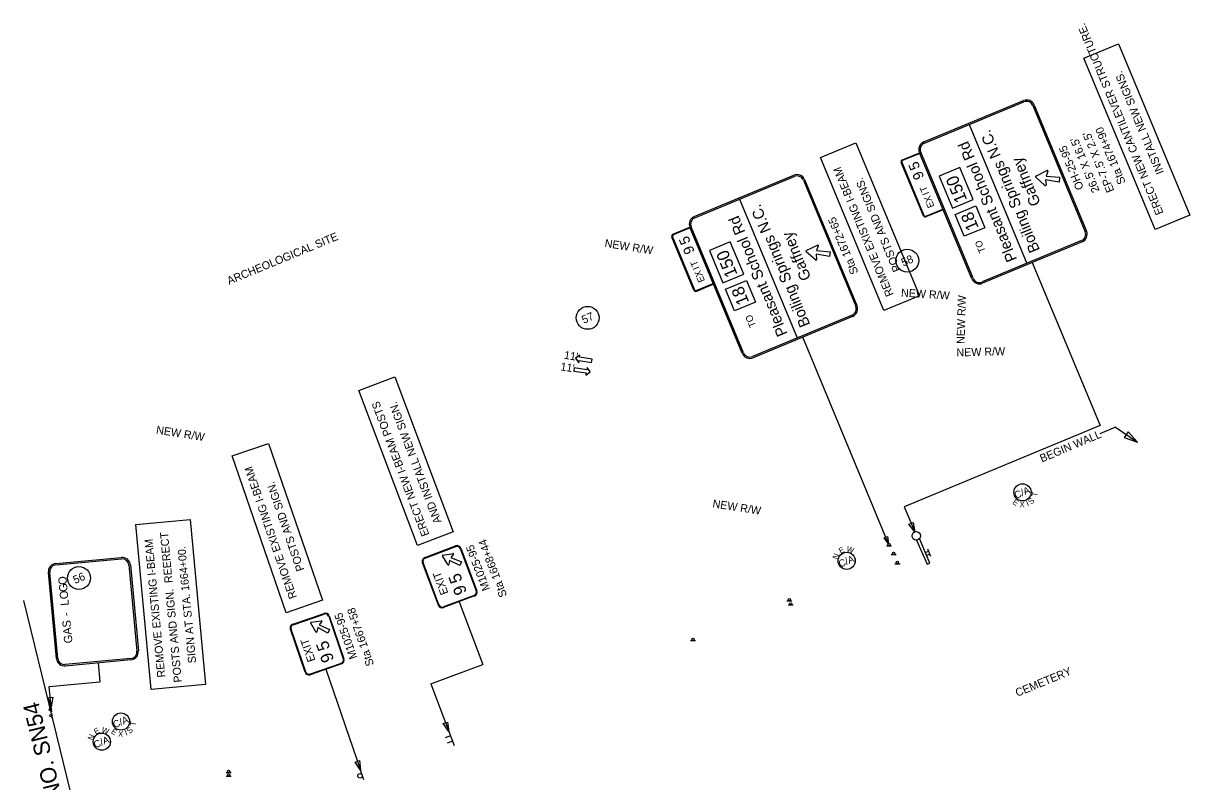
# Model space of a CAD drawing. Extents: x 1813391 to 1815007, y 1189909 to 1191222.
# Drawn here: x 1813391 to 1814411, y 1190407 to 1191071 of the extents above; entities that cross this region are included whole.
import ezdxf

# ---------------------------------------------------------------- set-up
doc = ezdxf.new("R2010")
doc.units = 0
for name, color, linetype in [('RD_EX_DV_Prop_txCode', 7, 'Continuous'), ('RD_EX_DV_TX_Prop', 7, 'Continuous'), ('RD_PD_Final_LnLine', 7, 'Continuous'), ('RD_PD_Final_TX', 7, 'Continuous'), ('RD_PD_RW_TX', 7, 'Continuous'), ('RD_SHT_MatchLine', 7, 'Continuous'), ('RD_SHT_TX', 7, 'Continuous'), ('RD_Sketch10', 7, 'Continuous'), ('RD_Sketch8', 7, 'Continuous'), ('SN_P_Signs', 7, 'Continuous'), ('TERMINATOR', 7, 'Continuous')]:
    doc.layers.add(name, color=color, linetype=linetype)

# ---------------------------------------------------------------- blocks, each defined once
blk = doc.blocks.new('SARRW2')
at = {"layer": 'RD_PD_Final_LnLine'}
blk.add_lwpolyline([(-12, 1.2), (-12, -1.2), (-2.83, -1.2), (-2.83, -2.83), (0, 0), (-2.83, 2.83), (-2.83, 1.2)], close=True, dxfattribs=at)

msp = doc.modelspace()

# ---------------------------------------------------------------- linework, layer by layer
at = {"layer": 'RD_EX_DV_TX_Prop'}
for centre in [(1814164.1, 1190863), (1813884.5, 1190812.9), (1813439.4, 1190585.3)]:
    msp.add_circle(centre, 10, dxfattribs=at)
at = {"layer": 'RD_PD_Final_TX'}
for q in [(1814332.5, 1190711.4), (1814365.5, 1190704)]:
    msp.add_line((1814346.2, 1190717.2), q, dxfattribs=at)
at = {"layer": 'RD_SHT_MatchLine'}
msp.add_line((1813390.8, 1190565.5), (1813552.1, 1189908.7), dxfattribs=at)
at = {"layer": 'RD_Sketch10'}
for centre in [(1814111.1, 1190600.3), (1813459.4, 1190442.1)]:
    msp.add_circle(centre, 7.5, dxfattribs=at)
at = {"layer": 'RD_Sketch8'}
for centre in [(1814264.9, 1190660.3), (1813476.2, 1190459.7)]:
    msp.add_circle(centre, 7.5, dxfattribs=at)
at = {"layer": 'SN_P_Signs'}
for p, q in [((1814218.3, 1190982), (1814268.7, 1190860.6)), ((1814088.1, 1190953.1), (1814119.1, 1190966)), ((1814119.1, 1190966), (1814174.8, 1190832.1)), ((1814143.7, 1190819.2), (1814088.1, 1190953.1)), ((1814210.2, 1190944.5), (1814192, 1190936.9)), ((1814221.9, 1190916.4), (1814210.2, 1190944.5)), ((1814192, 1190936.9), (1814203.7, 1190908.8)), ((1814017.4, 1190916.7), (1814067.9, 1190795.4)), ((1814203.7, 1190908.8), (1814221.9, 1190916.4)), ((1814206, 1190903.2), (1814224.2, 1190910.8)), ((1814224.2, 1190910.8), (1814232.1, 1190891.8)), ((1814213.9, 1190884.3), (1814206, 1190903.2)), ((1814232.1, 1190891.8), (1814213.9, 1190884.3)), ((1814009.3, 1190879.3), (1813991.2, 1190871.7)), ((1814021, 1190851.1), (1814009.3, 1190879.3)), ((1813991.2, 1190871.7), (1814002.9, 1190843.6)), ((1814273.5, 1190861.3), (1814332.8, 1190718.7)), ((1814002.9, 1190843.6), (1814021, 1190851.1)), ((1814005.2, 1190838), (1814023.4, 1190845.5)), ((1814013, 1190819.1), (1814005.2, 1190838)), ((1814023.4, 1190845.5), (1814031.2, 1190826.6)), ((1814174.8, 1190832.1), (1814143.7, 1190819.2)), ((1814031.2, 1190826.6), (1814013, 1190819.1)), ((1814147.8, 1190615.3), (1814072.7, 1190796.1)), ((1813684.3, 1190749.4), (1813715.7, 1190761.3)), ((1813715.7, 1190761.3), (1813766.9, 1190625.6)), ((1813735.5, 1190613.7), (1813684.3, 1190749.4)), ((1814332.8, 1190718.7), (1814161.5, 1190647.5)), ((1813573.6, 1190692.1), (1813605.4, 1190703)), ((1813605.4, 1190703), (1813652.5, 1190565.8)), ((1813620.7, 1190554.9), (1813573.6, 1190692.1)), ((1814161.5, 1190647.5), (1814170.6, 1190625.6)), ((1813489.2, 1190632.1), (1813536.6, 1190636.5)), ((1813536.6, 1190636.5), (1813550, 1190492.1)), ((1813502.6, 1190487.7), (1813489.2, 1190632.1)), ((1813766.9, 1190625.6), (1813735.5, 1190613.7)), ((1813742, 1190603.2), (1813768.9, 1190613.4)), ((1814145.9, 1190613.4), (1814150.4, 1190613.4)), ((1813742.2, 1190602.6), (1813769.2, 1190612.8)), ((1813773, 1190611.1), (1813787, 1190574)), ((1813773.6, 1190611.3), (1813787.6, 1190574.2)), ((1814149.9, 1190605.8), (1814154.4, 1190605.8)), ((1814180, 1190607.7), (1814182.6, 1190608.8)), ((1814181.1, 1190605.2), (1814183.6, 1190606.3)), ((1814181.7, 1190610.7), (1814184.5, 1190604.3)), ((1813753.9, 1190561.5), (1813739.9, 1190598.6)), ((1813754.4, 1190561.7), (1813740.5, 1190598.8)), ((1814153.3, 1190597.8), (1814157.8, 1190597.8)), ((1813652.5, 1190565.8), (1813620.7, 1190554.9)), ((1813785.2, 1190570.1), (1813758.3, 1190560)), ((1813785.5, 1190569.6), (1813758.5, 1190559.4)), ((1813772, 1190564.5), (1813792.7, 1190509.7)), ((1814058.7, 1190565.3), (1814063.2, 1190565.3)), ((1813626.6, 1190545), (1813653.9, 1190554.3)), ((1813626.8, 1190544.4), (1813654.1, 1190553.8)), ((1813657.9, 1190551.9), (1813670.7, 1190514.5)), ((1813658.4, 1190552.1), (1813671.3, 1190514.6)), ((1814059.8, 1190561.7), (1814064.3, 1190561.7)), ((1813637.2, 1190503), (1813624.4, 1190540.4)), ((1813637.8, 1190503.2), (1813625, 1190540.6)), ((1813974.4, 1190530.6), (1813978.9, 1190530.6)), ((1813456.2, 1190511), (1813457.7, 1190494.5)), ((1813668.9, 1190510.6), (1813641.6, 1190501.3)), ((1813669.1, 1190510.1), (1813641.8, 1190500.7)), ((1813655.4, 1190505.4), (1813685.7, 1190417.1)), ((1813747.3, 1190492.6), (1813792.7, 1190509.7)), ((1813413.5, 1190490.3), (1813457.7, 1190494.5)), ((1813550, 1190492.1), (1813502.6, 1190487.7)), ((1813747.3, 1190492.6), (1813763, 1190450.9)), ((1813415.2, 1190472.6), (1813413.5, 1190490.3)), ((1813415.6, 1190468.1), (1813415.2, 1190472.6)), ((1813416.1, 1190462.6), (1813415.7, 1190467.1)), ((1813763, 1190450.9), (1813767.6, 1190438.7)), ((1813764.4, 1190447.3), (1813759.7, 1190445.5)), ((1813766.1, 1190442.6), (1813761.5, 1190440.8)), ((1813568.1, 1190415.1), (1813572.6, 1190415.1)), ((1813568.1, 1190412), (1813572.6, 1190412)), ((1813688.7, 1190408.6), (1813685.7, 1190417.1))]:
    msp.add_line(p, q, dxfattribs=at)
for points in [[(1814380.9, 1190890.1), (1814318.6, 1191040.1), (1814348.9, 1191052.7), (1814411.2, 1190902.7)], [(1814169.2, 1190634), (1814170.6, 1190625.6), (1814165.4, 1190632.3)], [(1814146.9, 1190621.6), (1814147.8, 1190615.3), (1814144, 1190620.4)], [(1813416.5, 1190480.9), (1813415.2, 1190472.6), (1813412.4, 1190480.5)], [(1813762, 1190459.3), (1813763, 1190450.9), (1813758.2, 1190457.9)], [(1813685, 1190425.6), (1813685.7, 1190417.1), (1813681.1, 1190424.2)]]:
    msp.add_lwpolyline(points, close=True, dxfattribs=at)
for points in [[(1814178.7, 1190966.8), (1814265.7, 1191003)], [(1814179.1, 1190965.7), (1814266.2, 1191001.9)], [(1814274, 1190998.6), (1814319.8, 1190888.3)], [(1814275.1, 1190999.1), (1814321, 1190888.8)], [(1814159.8, 1190951.2), (1814174.8, 1190957.4), (1814175, 1190956.8)], [(1814175, 1190956.8), (1814160, 1190950.6)], [(1814220.6, 1190847.1), (1814174.8, 1190957.4)], [(1814221.7, 1190847.5), (1814175.9, 1190957.9)], [(1814178.2, 1190902.3), (1814158.8, 1190948.8)], [(1814159.4, 1190949.1), (1814178.7, 1190902.5)], [(1814276.6, 1190937), (1814286.3, 1190941.8)], [(1814287.2, 1190941.1), (1814285.6, 1190936.9)], [(1813977.8, 1190901.6), (1814064.9, 1190937.8)], [(1813978.3, 1190900.5), (1814065.3, 1190936.7)], [(1814073.2, 1190933.4), (1814119, 1190823.1)], [(1814074.3, 1190933.9), (1814120.1, 1190823.6)], [(1814284.6, 1190928.8), (1814276.5, 1190936)], [(1814297.4, 1190935.9), (1814296.9, 1190931.7), (1814285.2, 1190933.7)], [(1814285.2, 1190933.7), (1814285.6, 1190929.3)], [(1814285.6, 1190936.9), (1814297.4, 1190935.9)], [(1814180.3, 1190901.9), (1814195.3, 1190908.1), (1814195.5, 1190907.5), (1814180.5, 1190901.3)], [(1813959, 1190886), (1813973.9, 1190892.2), (1813974.2, 1190891.6)], [(1813974.2, 1190891.6), (1813959.2, 1190885.4)], [(1814019.8, 1190781.9), (1813973.9, 1190892.2)], [(1814020.9, 1190782.3), (1813975, 1190892.6)], [(1813977.3, 1190837.1), (1813958, 1190883.6)], [(1813958.6, 1190883.8), (1813977.9, 1190837.3)], [(1814316.6, 1190880.5), (1814229.6, 1190844.3)], [(1814317.1, 1190879.4), (1814230, 1190843.2)], [(1814083.8, 1190863.6), (1814075.7, 1190870.8)], [(1814075.8, 1190871.8), (1814085.5, 1190876.6)], [(1814096.6, 1190870.7), (1814096, 1190866.5), (1814084.3, 1190868.5)], [(1814084.3, 1190868.5), (1814084.8, 1190864.1)], [(1814086.3, 1190875.9), (1814084.7, 1190871.7)], [(1814084.7, 1190871.7), (1814096.6, 1190870.7)], [(1813979.5, 1190836.7), (1813994.4, 1190842.9), (1813994.7, 1190842.3), (1813979.7, 1190836.1)], [(1814115.8, 1190815.3), (1814028.7, 1190779.1)], [(1814116.2, 1190814.2), (1814029.2, 1190778)], [(1814172.3, 1190618.5), (1814181.5, 1190597.3), (1814184, 1190598.4), (1814174.8, 1190619.8)], [(1813419.2, 1190597.9), (1813476.5, 1190603.3)], [(1813762.2, 1190597), (1813757.5, 1190604.6)], [(1813757.8, 1190605.3), (1813766.7, 1190606.8)], [(1813767.1, 1190606.1), (1813764.8, 1190603.2)], [(1813764.8, 1190603.2), (1813774.2, 1190599.5)], [(1813419.3, 1190596.7), (1813476.6, 1190602.1)], [(1813483.2, 1190596.7), (1813490.2, 1190521.4)], [(1813484.4, 1190596.8), (1813491.4, 1190521.5)], [(1813763.7, 1190600.7), (1813763.1, 1190597.1)], [(1813774.2, 1190599.5), (1813772.7, 1190596.2), (1813763.7, 1190600.7)], [(1813419.7, 1190514.8), (1813412.7, 1190590.1)], [(1813420.9, 1190514.9), (1813413.9, 1190590.2)], [(1813646.7, 1190538.1), (1813642.2, 1190545.9)], [(1813642.5, 1190546.6), (1813651.4, 1190547.8)], [(1813648.3, 1190541.9), (1813647.5, 1190538.3)], [(1813658.7, 1190540.3), (1813657.1, 1190537), (1813648.3, 1190541.9)], [(1813651.8, 1190547.1), (1813649.5, 1190544.3)], [(1813649.5, 1190544.3), (1813658.7, 1190540.3)], [(1813484.8, 1190514.9), (1813427.4, 1190509.5)], [(1813484.9, 1190513.7), (1813427.5, 1190508.3)]]:
    msp.add_lwpolyline(points, dxfattribs=at)
for centre, radius in [((1814172, 1190622.2), 3.71), ((1814148.2, 1190614.4), 1), ((1814152.1, 1190606.8), 1), ((1814155.5, 1190598.9), 1), ((1814061, 1190566.3), 1), ((1814062, 1190562.7), 1), ((1813976.7, 1190531.6), 1), ((1813414.4, 1190470.2), 1), ((1813414.9, 1190464.8), 1), ((1813570.3, 1190416.1), 1), ((1813570.4, 1190413), 1), ((1813685.3, 1190412.2), 2)]:
    msp.add_circle(centre, radius, dxfattribs=at)
for centre, radius, start, end in [((1814268.5, 1190996.3), 7.2, 22.5666, 112.5666), ((1814268.5, 1190996.3), 6, 22.5666, 112.5666), ((1814181.4, 1190960.2), 7.2, 112.5666, 202.5666), ((1814181.4, 1190960.2), 6, 112.5666, 202.5666), ((1814160.5, 1190949.5), 1.8, 112.5666, 202.5666), ((1814160.5, 1190949.5), 1.2, 112.5666, 202.5666), ((1814286.6, 1190941.3), 0.6, 339.1205, 116.586), ((1814067.6, 1190931.1), 7.2, 22.5666, 112.5666), ((1814067.6, 1190931.1), 6, 22.5666, 112.5666), ((1814276.9, 1190936.4), 0.6, 116.586, 228.5473), ((1814285, 1190929.2), 0.6, 228.5473, 6.0127), ((1813980.6, 1190894.9), 7.2, 112.5666, 202.5666), ((1813980.6, 1190894.9), 6, 112.5666, 202.5666), ((1814179.8, 1190903), 1.8, 202.5666, 292.5666), ((1814179.8, 1190903), 1.2, 202.5666, 292.5666), ((1814314.3, 1190886), 7.2, 292.5666, 22.5666), ((1813959.7, 1190884.3), 1.8, 112.5666, 202.5666), ((1813959.7, 1190884.3), 1.2, 112.5666, 202.5666), ((1814314.3, 1190886), 6, 292.5666, 22.5666), ((1814076.1, 1190871.2), 0.6, 116.586, 228.5473), ((1814085.8, 1190876.1), 0.6, 339.1205, 116.586), ((1814084.2, 1190864), 0.6, 228.5473, 6.0127), ((1814227.3, 1190849.8), 7.2, 202.5666, 292.5666), ((1814227.3, 1190849.8), 6, 202.5666, 292.5666), ((1813979, 1190837.8), 1.8, 202.5666, 292.5666), ((1813979, 1190837.8), 1.2, 202.5666, 292.5666), ((1814113.5, 1190820.8), 6, 292.5666, 22.5666), ((1814113.5, 1190820.8), 7.2, 292.5666, 22.5666), ((1814026.4, 1190784.6), 7.2, 202.5666, 292.5666), ((1814026.4, 1190784.6), 6, 202.5666, 292.5666), ((1813770.2, 1190610), 3.6, 20.6671, 110.6671), ((1813770.2, 1190610), 3, 20.6671, 110.6671), ((1813477.2, 1190596.1), 7.2, 5.3197, 95.3197), ((1813743.3, 1190599.8), 3.6, 110.6671, 200.6671), ((1813757.9, 1190604.9), 0.45, 99.4892, 211.845), ((1813766.8, 1190606.3), 0.45, 321.705, 99.4892), ((1813419.8, 1190590.8), 7.2, 95.3197, 185.3197), ((1813419.8, 1190590.8), 6, 95.3197, 185.3197), ((1813477.2, 1190596.1), 6, 5.3197, 95.3197), ((1813743.3, 1190599.8), 3, 110.6671, 200.6671), ((1813762.6, 1190597.2), 0.45, 211.845, 349.6292), ((1813784.2, 1190572.9), 3, 290.6671, 20.6671), ((1813784.2, 1190572.9), 3.6, 290.6671, 20.6671), ((1813655, 1190550.9), 3.6, 18.9395, 108.9395), ((1813655, 1190550.9), 3, 18.9395, 108.9395), ((1813757.2, 1190562.8), 3.6, 200.6671, 290.6671), ((1813757.2, 1190562.8), 3, 200.6671, 290.6671), ((1813627.8, 1190541.6), 3.6, 108.9395, 198.9395), ((1813627.8, 1190541.6), 3, 108.9395, 198.9395), ((1813642.5, 1190546.2), 0.45, 97.7616, 210.1174), ((1813651.5, 1190547.4), 0.45, 319.9774, 97.7616), ((1813647.1, 1190538.4), 0.45, 210.1174, 347.9016), ((1813484.2, 1190520.8), 6, 275.3197, 5.3197), ((1813484.2, 1190520.8), 7.2, 275.3197, 5.3197), ((1813426.9, 1190515.5), 7.2, 185.3197, 275.3197), ((1813426.9, 1190515.5), 6, 185.3197, 275.3197), ((1813667.9, 1190513.5), 3, 288.9395, 18.9395), ((1813667.9, 1190513.5), 3.6, 288.9395, 18.9395), ((1813640.7, 1190504.1), 3.6, 198.9395, 288.9395), ((1813640.7, 1190504.1), 3, 198.9395, 288.9395)]:
    msp.add_arc(centre, radius, start, end, dxfattribs=at)
at = {"layer": 'TERMINATOR'}
msp.add_lwpolyline([(1814353.9, 1190708.3), (1814365.5, 1190704), (1814357.3, 1190713.2)], close=True, dxfattribs=at)

# ---------------------------------------------------------------- block references
at = {"layer": 'RD_PD_Final_LnLine'}
for p, xscale, yscale, rotation in [((1813873.9, 1190777.5), 1.2000000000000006, 1.2000000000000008, 171.59372332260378), ((1813886.8, 1190765.6), 1.2000000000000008, 1.200000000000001, -8.40627667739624)]:
    msp.add_blockref('SARRW2', p, dxfattribs=dict(at, xscale=xscale, yscale=yscale, rotation=rotation))

# ---------------------------------------------------------------- texts
at = {"layer": 'RD_EX_DV_Prop_txCode'}
for s, p in [('58', (1814160.7, 1190857.7)), ('57', (1813881.1, 1190807.6)), ('56', (1813436.1, 1190580))]:
    msp.add_text(s, height=7, rotation=23.7538, dxfattribs=at).set_placement(p)
at = {"layer": 'RD_PD_Final_TX'}
for s, rotation, p in [('ARCHEOLOGICAL SITE', 22.4268, (1813570.7, 1190841.8)), ("11'", 350.8557, (1813863.4, 1190777.2)), ("11'", 350.8557, (1813860.3, 1190767.1)), ('BEGIN WALL', 22.8166, (1814281.9, 1190686.3)), ('CEMETERY', 22.4268, (1814260.4, 1190481.3))]:
    msp.add_text(s, height=7, rotation=rotation, dxfattribs=at).set_placement(p)
at = {"layer": 'RD_PD_RW_TX'}
for rotation, p in [(351.0437, (1813899, 1190875)), (356.3248, (1814158.5, 1190831.6)), (88.2894, (1814214.2, 1190790)), (1.5746, (1814207.2, 1190779.1)), (351.0437, (1813506.6, 1190711.7)), (351.0437, (1813993.4, 1190647.2))]:
    msp.add_text('NEW R/W', height=7, rotation=rotation, dxfattribs=at).set_placement(p)
at = {"layer": 'RD_SHT_TX'}
msp.add_text('MATCHLINE STA. 1665+00 SEE SHEET NO. SN54', height=14.173, rotation=103.9067, dxfattribs=at).set_placement((1813509.6, 1190050.9))
at = {"layer": 'RD_Sketch10'}
for s, height, rotation, p in [('W', 5, 341.8692, (1814110.5, 1190608.6)), ('N', 5, 67.4364, (1814103, 1190601.1)), ('E', 5, 26.8996, (1814105.8, 1190606.4)), ('C/A', 6.25, 22.5666, (1814105.5, 1190594.4)), ('E', 5, 26.8996, (1813454.1, 1190448.2)), ('W', 5, 341.8692, (1813458.8, 1190450.4)), ('N', 5, 67.4364, (1813451.4, 1190442.9)), ('C/A', 6.25, 22.5666, (1813453.8, 1190436.2))]:
    msp.add_text(s, height=height, rotation=rotation, dxfattribs=at).set_placement(p)
at = {"layer": 'RD_Sketch8'}
for s, height, rotation, p in [('C/A', 6.25, 22.5666, (1814259.3, 1190654.5)), ('E', 5, 325.7778, (1814255.7, 1190650.6)), ('S', 5, 44.359, (1814272.7, 1190649.4)), ('T', 5, 80.7517, (1814277.7, 1190656.2)), ('X', 5, 358.2072, (1814262.3, 1190647.2)), ('I', 5, 22.3672, (1814269.4, 1190647.9)), ('C/A', 6.25, 22.5666, (1813470.6, 1190453.8)), ('T', 5, 80.7517, (1813488.9, 1190455.5)), ('E', 5, 325.7778, (1813467, 1190449.9)), ('X', 5, 358.2072, (1813473.6, 1190446.5)), ('I', 5, 22.3672, (1813480.7, 1190447.2)), ('S', 5, 44.359, (1813484, 1190448.7))]:
    msp.add_text(s, height=height, rotation=rotation, dxfattribs=at).set_placement(p)
at = {"layer": 'SN_P_Signs'}
for s, height, rotation, p in [('ERECT NEW CANTILEVER STRUCTURE.', 7, 112.5667, (1814388.4, 1190904.7)), ('INSTALL NEW SIGNS.', 7, 112.5667, (1814388.8, 1190940.2)), ('Boiling Springs N.C.', 9.6, 112.5666, (1814280.3, 1190872.3)), ("EP-7.5' X 2.5'", 7, 112.5667, (1814345.4, 1190924.3)), ('Sta 1674+90', 7, 112.5667, (1814355.3, 1190931.4)), ('Pleasant School Rd', 9.6, 112.5666, (1814260.4, 1190864.2)), ('OH-25-95', 7, 112.5667, (1814318.7, 1190926.5)), ("26.5' X 16.5'", 7, 112.5667, (1814332.6, 1190924.1)), ('Gaffney', 9.6, 112.5666, (1814281, 1190913)), ('REMOVE EXISTING I-BEAM', 7, 112.5667, (1814152.3, 1190833.3)), ('5', 9, 112.5666, (1814175.6, 1190944.4)), ('9', 9, 112.5666, (1814179.1, 1190936)), ('POSTS AND SIGNS.', 7, 112.5667, (1814158.6, 1190854.8)), ('150', 10.8, 112.5666, (1814216.7, 1190916.3)), ('T', 6, 112.5666, (1814182.3, 1190924.4)), ('I', 6, 112.5666, (1814183.4, 1190921.7)), ('X', 6, 112.5666, (1814186.1, 1190915.4)), ('Boiling Springs N.C.', 9.6, 112.5666, (1814079.4, 1190807.1)), ('E', 6, 112.5666, (1814188, 1190910.6)), ('Pleasant School Rd', 9.6, 112.5666, (1814059.6, 1190799)), ('Sta 1672+65', 7, 112.5667, (1814121.4, 1190852.6)), ('18', 10.8, 112.5666, (1814226.8, 1190891.9)), ('5', 9, 112.5666, (1813974.8, 1190879.2)), ('Gaffney', 9.6, 112.5666, (1814080.2, 1190847.8)), ('TO', 6, 112.5666, (1814232.8, 1190871.2)), ('9', 9, 112.5666, (1813978.3, 1190870.8)), ('150', 10.8, 112.5666, (1814015.8, 1190851)), ('T', 6, 112.5666, (1813981.5, 1190859.2)), ('I', 6, 112.5666, (1813982.6, 1190856.5)), ('X', 6, 112.5666, (1813985.2, 1190850.2)), ('E', 6, 112.5666, (1813987.2, 1190845.4)), ('18', 10.8, 112.5666, (1814026, 1190826.7)), ('TO', 6, 112.5666, (1814032, 1190806)), ('ERECT NEW I-BEAM POSTS', 7, 110.6672, (1813746.1, 1190623.3)), ('AND INSTALL NEW SIGN.', 7, 110.6672, (1813756.8, 1190634.5)), ('REMOVE EXISTING I-BEAM', 7, 108.9396, (1813630.2, 1190568.5)), ('POSTS AND SIGN.', 7, 108.9396, (1813636.7, 1190592.6)), ('POSTS AND SIGN.  REERECT', 7, 95.3198, (1813529.5, 1190494.2)), ('REMOVE EXISTING I-BEAM', 7, 95.3198, (1813515, 1190498.6)), ('M1025-95', 7, 110.6672, (1813799.2, 1190575.6)), ('Sta 1668+44', 7, 110.6672, (1813814.1, 1190570)), ('SIGN AT STA. 1664+00.', 7, 95.3198, (1813542, 1190511.1)), ('O', 7.2, 95.3197, (1813429, 1190579.7)), ('O', 7.2, 95.3197, (1813429, 1190579.7)), ('EXIT', 7, 110.6671, (1813762.7, 1190572.1)), ('5', 10.8, 110.6671, (1813775.2, 1190583)), ('G', 7.2, 95.3197, (1813429.6, 1190573.5)), ('G', 7.2, 95.3197, (1813429.6, 1190573.5)), ('O', 7.2, 95.3197, (1813430.2, 1190567.1)), ('O', 7.2, 95.3197, (1813430.2, 1190567.1)), ('9', 10.8, 110.6671, (1813779.1, 1190572.8)), ('L', 7.2, 95.3197, (1813430.7, 1190561.4)), ('L', 7.2, 95.3197, (1813430.7, 1190561.4)), ('-', 7.2, 95.3197, (1813431.6, 1190552.1)), ('-', 7.2, 95.3197, (1813431.6, 1190552.1)), ('M1025-95', 7, 108.9396, (1813683, 1190515.7)), ('Sta 1667+58', 7, 108.9396, (1813697.7, 1190509.6)), ('GAS', 7.2, 95.3197, (1813433.8, 1190528.5)), ('EXIT', 7, 108.9395, (1813646.4, 1190513.3)), ('5', 10.8, 108.9395, (1813659.3, 1190523.8)), ('9', 10.8, 108.9395, (1813662.8, 1190513.5))]:
    msp.add_text(s, height=height, rotation=rotation, dxfattribs=at).set_placement(p)

doc.saveas('drawing.dxf')
